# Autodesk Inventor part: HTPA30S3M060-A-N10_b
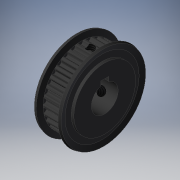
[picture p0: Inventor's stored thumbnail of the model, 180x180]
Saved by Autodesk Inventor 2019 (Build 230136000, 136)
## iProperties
Created: 2022-11
Part Number: HTPA30S3M060-A-N10_b
Material: Generic
Catalog Web Link: www.cadenas.de
Description: HTPA__S3M060, HTPA__S3M100, HTPA__S3M150, HTPB__S3M060, HTPB__S3M100, HTPB__S3M150, HTPK__S3M060, HTPK__S3M100, HTPK__S3M150, HTPN__S3M060, HTPN__S3M100, HTPN__
Vendor: MISUMI
Document SubType Name: Modeling
Designer: psAdmin
Manufacturer: MISUMI
Mass: 5.31734 g
Surface Area: 36.0109 cm^2
Volume: 5.31734 cm^3
Density: 1 g/cm^3
Appearance: PSOLRGB-175-175-175
Category: PARTsolutions
Company: MISUMI
Title: HTPA30S3M060-A-N10
Author: Cadenas PARTsolutions
Comments: High Torque Timing Pulleys S3M Type
PSOL_IDENT_0: {$CADENAS_DATA/23d-libs/misumi/metric/51_timing_pulleys/htpk_s3m/htpa_s3m.prj},837 {VTYP=3D},{NB=HTP
PSOL_IDENT_1: A30S3M060-A-N10_b},{LINA=HTPA30S3M060-A-N10},{NN=HTPA__S3M060, HTPA__S3M100, HTPA__S3M150, HTPB__S3M
PSOL_IDENT_2: 060, HTPB__S3M100, HTPB__S3M150, HTPK__S3M060, HTPK__S3M100, HTPK__S3M150, HTPN__S3M060, HTPN__S3M10
PSOL_IDENT_3: 0, HTPN__S3M150, HTPT__S3M060, HTPT__S3M100, HTPT__S3M150, HTPM__S3M060, HTPM__S3M100, HTPM__S3M150,
PSOL_IDENT_4: HTPP__S3M060, HTPP__S3M100, HTPP__S3M150, HTPS__S3M060, HTPS__S3M100, KHTPA__S3M060, KHTPA__S3M100,
PSOL_IDENT_5: KHTPA__S3M150, KHTPK__S3M060, KHTPK__S3M100, KHTPK__S3M150_body},{DATE=28.10.2022 00:10:57},{GEOMDA
PSOL_IDENT_6: TE=11.11.2021 09:52:43},{VERSION=},{LINEID=160},{WBVAR=MATP,ST,TNW,PS,SBS,DD,Z,J,Q,R,S,T,ALT1,ALT2,M
PSOL_IDENT_7: ,QSC,QFC,QTC,ALT3,K,KSC,KFC,KTC,ALT4,ZM,ZSC,ZFC,ZTC,ALT5,ALT6,ALT7,FC,ALT8,SRG,ALT9,BTC,TL,ALT10,TPC
PSOL_IDENT_8: ,ALT11,BC,ALT12,SLH,ALT13,BN},{WBNUMERIC=DD,Z,J,Q,R,S,T,QSC,QFC,QTC,K,KSC,KFC,KTC,ZSC,ZFC,ZTC,FC,SRG
PSOL_IDENT_9: ,BTC,TL,BC,SLH,BN}  {NB=HTPA30S3M060-A-N10_b},{LINA=HTPA30S3M060-A-N10},{KT=DUMMY},{PN=HTPA30S3M060-
PSOL_IDENT_10: A-N10},{TYPE=HTPA},{MATP=A2017},{MATPALG='A2017','Aluminum Alloy 2000 series','S45C','1045 Carbon St
PSOL_IDENT_11: eel Equivalent','SUS304','304 Stainless Steel','A6000','6000 Series Aluminum Alloy'},{ST=CA},{STALG=
PSOL_IDENT_12: 'CA','Clear Anodize','BA','Black Anodize','HAT','Hard Clear Anodize','ENP','Electroless Nickel Plat
PSOL_IDENT_13: ing' },{NT=30},{TNW=S3M060},{TNWALG= 'S3M060','S3M100','S3M150'    },{BW=6},{PS=A},{PSALG='A','B'},{
PSOL_IDENT_14: SBS=N},{SBSALG= 'H','Round Hole','P','Round Hole + Tap','N','New JIS Keywayed Bore + Tap (Standard)'
PSOL_IDENT_15: ,'NK','New JIS Keywayed Bore + Tap (width 4.0mm, height 1.8mm)','C','Old JIS Keywayed Bore + Tap','V'
PSOL_IDENT_16: ,'Stepped Hole', 'Y','Both Ends Stepped Hole','WB', 'Double Stepped Hole' },{SHSA= 'H','Round Hole','
PSOL_IDENT_17: P','Round Hole + Tap','N','New JIS Keywayed Bore + Tap (Standard)','NK','New JIS Keywayed Bore + Tap
PSOL_IDENT_18: (width 4.0mm, height 1.8mm)','C','Old JIS Keywayed Bore + Tap','V','Stepped Hole', 'Y','Both Ends S
PSOL_IDENT_19: tepped Hole','WB', 'Double Stepped Hole' },{SHSB= 'H','Round Hole','P','Round Hole + Tap','N','New J
PSOL_IDENT_20: IS Keywayed Bore + Tap (Standard)','NK','New JIS Keywayed Bore + Tap (width 4.0mm, height 1.8mm)','C'
PSOL_IDENT_21: ,'Old JIS Keywayed Bore + Tap','V','Stepped Hole', 'F','Stepped Hole (Counterbore holes on the boss
PSOL_IDENT_22: side)'},{SHSK= '','' },{SBSPN=-N10},{DD=10.00},{DDALG=[8:8/1],[10:14/1]},{DDHA=[6:6/1],6.35,[7:12/1]
PSOL_IDENT_23: ,12.7,[13:19/1]},{DDHBK=0},{DDPA=[6:6/1],6.35,[7:12/1],12.7,[13:19/1]},{DDPBK=0},{DDNA=[8:8/1],[10:1
PSOL_IDENT_24: 4/1]},{DDNBK=0},{DDNK=10},{DDCA=[10:10/1],[12:12/1]},{DDCBK=0},{DDVA=[6:6/1],6.35,[7:12/1],12.7,[13:
PSOL_IDENT_25: 17/1]},{DDVF=[6:6/1],6.35,[7:12/1],12.7,[13:14/1]},{DDY=[6:17/1]},{DDWB=[6:15/1]},{Z=0},{ZALG=[0]},{
PSOL_IDENT_26: ZQRMIN=12},{ZAMAX=19},{ZBMAX=16},{DDZ=10},{J=0.0},{JALG=[0]},{JMAX=9},{JMIN=2},{JPN=},{QRMAX=19},{QR
PSOL_IDENT_27: MIN=12},{WBRMAX=-2.00},{WBQMIN=14},{Q=0},{QALG=[0]},{QPN=},{R=0},{RALG=[0]},{S=0.0},{SALG=[0]},{SPN=
PSOL_IDENT_28: },{SMAX=5},{T=0.0},{TALG=[0]},{TPN=},{TMAX=8},{A=7},{W=11},{L=0},{PD=28.65},{OD=27.89},{D=0},{DALG=2
PSOL_IDENT_29: 0},{DE=23},{F=32},{E=23},{BBK=3.000},{TTK=1.4},{TT=1},{ANG=120},{WL=11},{ALT1=},{ALT1ALG= '','w/o KC
PSOL_IDENT_30: 90 (Set Screw Angle)','KC90','with KC90 (Set Screw Angle)' },{ALT1PN=},{ALT2=},{ALT2ALG= '','Not app
PSOL_IDENT_31: licable' },{M=N/A},{MALG= 'N/A' },{MFTALG= 'N/A' },{MSALG= 'N/A' },{M3D=0.000},{KDML=0},{ML=0},{MUL=
PSOL_IDENT_32: 0},{PITCH=0},{QSC=0.0},{QSCALG=0},{QFC=0.0},{QFCALG=0},{QTC=0.0},{QTCALG=0},{QPCDMIN=0},{QPCDMINALG=
PSOL_IDENT_33: 0},{QPCDMAX=19},{ALT2PN=},{ALT3=},{ALT3ALG= '','Not applicable' },{K=0.0},{KALG=0},{KMIN=4},{KFTMAX=
PSOL_IDENT_34: 0.0},{KSMAX=0.0},{KSC=0.0},{KSCALG=0},{KFC=0.0},{KFCALG=0},{KTC=0.0},{KTCALG=0},{KPCDMIN=14},{KPCDMI
PSOL_IDENT_35: NALG=14},{KPCDMAX=19},{KSCMIN=14.0},{KSCMINALG=14},{ALT3PN=},{ALT4=},{ALT4ALG= '','Not applicable' }
PSOL_IDENT_36: ,{ALT4MIN=20.5},{ALT4MAX=12.5},{ZM=N/A},{ZMALG= 'N/A' },{ZMSALG= 'N/A' },{ZMFTALG= 'N/A' },{ZMDD1=0.
PSOL_IDENT_37: 0},{ZMDD2=0.0},{ZMHH=0.0},{ZSC=0.0},{ZSCALG=[0]},{ZFC=0.0},{ZFCALG=[0]},{ZTC=0.0},{ZTCALG=[0]},{ZPCD
PSOL_IDENT_38: MIN=0},{ZPCDMINALG=0},{ZPCDMAX=19},{ALT4PN=},{ALT5=},{ALT5ALG= '','Flange Attached','NFC','with NFC
PSOL_IDENT_39: (Flange not Attached)' },{ALT5PN=},{ALT6=},{ALT6ALG= '','w/o Flange Attached on One Side Only','RFC'
PSOL_IDENT_40: ,'with RFC (Flange Attached on The Boss Side Only)','LFC','with LFC (Flange Attached on The Opposite
PSOL_IDENT_41: Side Only)' },{ALT6PN=},{ALT7=},{ALT7ALG= '','w/o FC (Flange Cut)','FC','with FC (Flange Cut)' },{F
PSOL_IDENT_42: C=0.0},{FCALG=0},{FCMIN=29.0},{FCMAX=30.0},{ALT7PN=},{ALT8=},{ALT8ALG= '','Not applicable' },{ALT8AL
PSOL_IDENT_43: GALG=19},{ALT8DD2=0},{ALT8MM=0},{ALT8NN=0},{QC=0},{KC=0},{ZC=0},{SRG=0.0},{SRGALG=[0]},{SRGMAX1=0},{
PSOL_IDENT_44: SRGMAX=0},{DD2=0.0},{MM=0.00},{NN=0.00},{ALT8PN=},{ALT9ALG= '','Not applicable' },{ALT9=},{BTC9=11},
PSOL_IDENT_45: {TL9=1},{BTC=0},{BTCALG=[0]},{TL=0.0},{TLALG=0},{TLMIN=1.0},{TLMAX=-11.5},{BTCL=0},{BTCD=0},{BTCDALG=
PSOL_IDENT_46: 20.000},{ALT9PN=},{WLBCTL=11},{ALT10=},{ALT10ALG= '','w/o TPC (Tapped Hole Dimension)','TPC','with T
PSOL_IDENT_47: PC (Tapped Hole Dimension)' },{TPC=N/A},{TPCALG= 'N/A' },{TPCM=4},{ALT10PN=},{ALT11=},{ALT11ALG= '','
PSOL_IDENT_48: Not applicable' },{BC=0.0},{BCALG=0},{BCMIN=7},{BCMAX=-11.5},{BCPLANE=5.5},{M1WBC=5.5},{ALT11PN=},{A
PSOL_IDENT_49: LT12=},{ALT12ALG= '','w/o SLH (Set Screw Length)','SLH','with SLH (Set Screw Length)' },{SLH=0},{SLH
PSOL_IDENT_50: ALG=[0]},{ALT12PN=},{AC=M4x3},{M1=4},{M1L=3},{TAP=0.000},{KYY=5},{KTT=8.945},{PLANE=11},{CD=0},{ALT1
PSOL_IDENT_51: 3=},{ALT13ALG= '', 'Not applicable' },{BN=0.0},{BNALG=0},{BNMIN=-10.5},{BNMAX=-1.0},{ALT13PN=}
NB: HTPA30S3M060-A-N10_b
NN: 0
NT: 30
NBSYN: $PN._b
LINA: HTPA30S3M060-A-N10
CATALOG: Misumi
PN: HTPA30S3M060-A-N10
MATP: Aluminum Alloy 2000 series
ST: Clear Anodize
TNW: S3M060
BW: 6
PS: A
SBS: New JIS Keywayed Bore + Tap (Standard)
DD: 10
Z: 0
J: 0
Q: 0
R: 0
S: 0
T: 0
A: 7
W: 11
L: 0
PD: 28.65
OD: 27.89
D: 0
F: 32
E: 23
TT: 1
ALT1: w/o KC90 (Set Screw Angle)
ALT2: Not applicable
M: N/A
QSC: 0
QFC: 0
QTC: 0
ALT3: Not applicable
K: 0
KSC: 0
KFC: 0
KTC: 0
ALT4: Not applicable
ZM: N/A
ZMDD1: 0
ZMDD2: 0
ZMHH: 0
ZSC: 0
ZFC: 0
ZTC: 0
ALT5: Flange Attached
ALT6: w/o Flange Attached on One Side Only
ALT7: w/o FC (Flange Cut)
FC: 0
ALT8: Not applicable
SRG: 0
DD2: 0
MM: 0
ALT9: Not applicable
BTC: 0
TL: 0
BTCL: 0
BTCD: 0
ALT10: w/o TPC (Tapped Hole Dimension)
TPC: N/A
ALT11: Not applicable
BC: 0
ALT12: w/o SLH (Set Screw Length)
SLH: 0
AC: M4x3
ALT13: Not applicable
BN: 0
SUPPLIER: MISUMI
ARTICLENO: HTPA30S3M060-A-N10_b
BOMINFO: HTPA30S3M060-A-N10
CREATOR: CADENAS GmbH
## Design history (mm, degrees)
sketch "_____1"
  geometry: L1 (11, 0)-(0, 0); L2 (0, 0)-(0, 11.5); L3 (0, 11.5)-(1, 11.5); L4 (1, 11.5)-(1, 13.813); L5 (1, 13.813)-(0.483, 15.741); L6 (0.483, 15.741)-(1.449, 16); L7 (1.449, 16)-(2, 13.945); L8 (2, 13.945)-(9, 13.945); L9 (9, 13.945)-(9.551, 16); L10 (9.551, 16)-(10.517, 15.741); L11 (10.517, 15.741)-(10, 13.813); L12 (10, 13.813)-(10, 11.5); L13 (10, 11.5)-(11, 11.5); L14 (11, 11.5)-(11, 0); L15 (11, 0)-(0, 0)
  constraints: 30 end point
revolve "Revolution1" sketch "_____1" stored, may be unused: angle "d0" = 360 deg
sketch "Sketch2"
  geometry: 1 further point
hole "Hole1" sketch "Sketch2" at (0, 0) diameter "d1" = 10; stored, may be unused: countersink angle "d5" = 90 deg, drill point angle "d7" = 0 deg; dims "d2" = 6, "d3" = 4, "d4" = 2, "d6" = 11
sketch "_____6"
  geometry: C1 r 18.945 at (0, 0); A1 r 13.945 centre (0, 0) between (-13.943, 0.259) and (-13.943, -0.259); A2 r 0.28 centre (-13.663, -0.254) between (-13.943, -0.259) and (-13.718, -0.528); A3 r 1.975 centre (-14.112, -2.464) between (-12.845, -0.948) and (-13.718, -0.528); A4 r 0.15 centre (-12.941, -1.063) between (-12.792, -1.051) and (-12.845, -0.948); A5 r 12.835 centre (0, 0) between (-12.792, -1.051) and (-12.731, -1.632); A6 r 0.15 centre (-12.88, -1.651) between (-12.762, -1.743) and (-12.731, -1.632); A7 r 1.975 centre (-14.315, -0.524) between (-13.528, -2.336) and (-12.762, -1.743); A8 r 0.28 centre (-13.417, -2.592) between (-13.528, -2.336) and (-13.692, -2.646); A9 r 13.945 centre (0, 0) between (-13.692, -2.646) and (-13.584, -3.152); A10 r 0.28 centre (-13.311, -3.089) between (-13.584, -3.152) and (-13.309, -3.369); A11 r 1.975 centre (-13.291, -5.344) between (-12.367, -3.598) and (-13.309, -3.369); A12 r 0.15 centre (-12.438, -3.731) between (-12.294, -3.687) and (-12.367, -3.598); A13 r 12.835 centre (0, 0) between (-12.294, -3.687) and (-12.113, -4.243); A14 r 0.15 centre (-12.255, -4.293) between (-12.12, -4.359) and (-12.113, -4.243); A15 r 1.975 centre (-13.894, -3.489) between (-12.747, -5.097) and (-12.12, -4.359); A16 r 0.28 centre (-12.585, -5.325) between (-12.747, -5.097) and (-12.842, -5.434); A17 r 13.945 centre (0, 0) between (-12.842, -5.434) and (-12.632, -5.907); A18 r 0.28 centre (-12.378, -5.789) between (-12.632, -5.907) and (-12.318, -6.062); A19 r 1.975 centre (-11.89, -7.99) between (-11.349, -6.091) and (-12.318, -6.062); A20 r 0.15 centre (-11.39, -6.235) between (-11.259, -6.163) and (-11.349, -6.091); A21 r 12.835 centre (0, 0) between (-11.259, -6.163) and (-10.967, -6.669); A22 r 0.15 centre (-11.095, -6.747) between (-10.949, -6.783) and (-10.967, -6.669); A23 r 1.975 centre (-12.865, -6.302) between (-11.409, -7.636) and (-10.949, -6.783); A24 r 0.28 centre (-11.202, -7.825) between (-11.409, -7.636) and (-11.432, -7.986); A25 r 13.945 centre (0, 0) between (-11.432, -7.986) and (-11.128, -8.405); A26 r 0.28 centre (-10.904, -8.236) between (-11.128, -8.405) and (-10.788, -8.491); A27 r 1.975 centre (-9.968, -10.288) between (-9.835, -8.317) and (-10.788, -8.491); A28 r 0.15 centre (-9.845, -8.467) between (-9.731, -8.369) and (-9.835, -8.317); A29 r 12.835 centre (0, 0) between (-9.731, -8.369) and (-9.34, -8.803); A30 r 0.15 centre (-9.45, -8.906) between (-9.3, -8.912) and (-9.34, -8.803); A31 r 1.975 centre (-11.273, -8.839) between (-9.572, -9.841) and (-9.3, -8.912); A32 r 0.28 centre (-9.331, -9.984) between (-9.572, -9.841) and (-9.522, -10.188); A33 r 13.945 centre (0, 0) between (-9.522, -10.188) and (-9.137, -10.535); A34 r 0.28 centre (-8.954, -10.323) between (-9.137, -10.535) and (-8.787, -10.548); A35 r 1.975 centre (-7.612, -12.135) between (-7.891, -10.18) and (-8.787, -10.548); A36 r 0.15 centre (-7.869, -10.329) between (-7.779, -10.209) and (-7.891, -10.18); A37 r 12.835 centre (0, 0) between (-7.779, -10.209) and (-7.306, -10.553); A38 r 0.15 centre (-7.391, -10.676) between (-7.244, -10.65) and (-7.306, -10.553); A39 r 1.975 centre (-9.189, -10.989) between (-7.317, -11.616) and (-7.244, -10.65); A40 r 0.28 centre (-7.051, -11.705) between (-7.317, -11.616) and (-7.196, -11.945); A41 r 13.945 centre (0, 0) between (-7.196, -11.945) and (-6.747, -12.204); A42 r 0.28 centre (-6.612, -11.959) between (-6.747, -12.204) and (-6.402, -12.145); A43 r 1.975 centre (-4.922, -13.453) between (-5.602, -11.598) and (-6.402, -12.145); A44 r 0.15 centre (-5.55, -11.739) between (-5.486, -11.604) and (-5.602, -11.598); A45 r 12.835 centre (0, 0) between (-5.486, -11.604) and (-4.952, -11.841); A46 r 0.15 centre (-5.01, -11.98) between (-4.871, -11.924) and (-4.952, -11.841); A47 r 1.975 centre (-6.704, -12.66) between (-4.741, -12.884) and (-4.871, -11.924); A48 r 0.28 centre (-4.463, -12.916) between (-4.741, -12.884) and (-4.555, -13.18); A49 r 13.945 centre (0, 0) between (-4.555, -13.18) and (-4.062, -13.34); A50 r 0.28 centre (-3.981, -13.072) between (-4.062, -13.34) and (-3.737, -13.21); A51 r 1.975 centre (-2.018, -14.182) between (-3.068, -12.509) and (-3.737, -13.21); A52 r 0.15 centre (-2.988, -12.637) between (-2.954, -12.491) and (-3.068, -12.509); A53 r 12.835 centre (0, 0) between (-2.954, -12.491) and (-2.382, -12.612); A54 r 0.15 centre (-2.41, -12.759) between (-2.285, -12.676) and (-2.382, -12.612); A55 r 1.975 centre (-3.925, -13.777) between (-1.959, -13.588) and (-2.285, -12.676); A56 r 0.28 centre (-1.68, -13.561) between (-1.959, -13.588) and (-1.715, -13.839); A57 r 13.945 centre (0, 0) between (-1.715, -13.839) and (-1.2, -13.893); A58 r 0.28 centre (-1.176, -13.614) between (-1.2, -13.893) and (-0.909, -13.698); A59 r 1.975 centre (0.975, -14.292) between (-0.4, -12.874) and (-0.909, -13.698); A60 r 0.15 centre (-0.295, -12.982) between (-0.292, -12.832) and (-0.4, -12.874); A61 r 12.835 centre (0, 0) between (-0.292, -12.832) and (0.292, -12.832); A62 r 0.15 centre (0.295, -12.982) between (0.4, -12.874) and (0.292, -12.832); A63 r 1.975 centre (-0.975, -14.292) between (0.909, -13.698) and (0.4, -12.874); A64 r 0.28 centre (1.176, -13.614) between (0.909, -13.698) and (1.2, -13.893)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; 1 further point
  constraints: 480 point on circle, 241 centre point
extrude "Extrusion1" cut sketch "_____6" distance "d8" = 7; taper "d9" = 0 deg
sketch "_____10"
  geometry: L1 (-1.5, 6.4)-(-1.5, 0); L2 (-1.5, 0)-(1.5, 0); L3 (1.5, 0)-(1.5, 6.4); L4 (1.5, 6.4)-(-1.5, 6.4)
  constraints: 8 end point
extrude "Extrusion2" cut sketch "_____10" distance "d10" = 11; taper "d11" = 0 deg
sketch "_____18"
  geometry: L1 (0, 0)-(0, 13.945); L2 (0, 13.945)-(1.621, 13.945); L3 (1.621, 13.945)-(1.621, 0); L4 (1.621, 0)-(0, 0); L5 (0, 0)-(0, 13.945)
  constraints: 10 end point
revolve "Revolution2" sketch "_____18" stored, may be unused: angle "d12" = 360 deg
thread "Thread1" dims "d13" = 8.945, "d14" = 0
sketch "_____19"
  geometry: L1 (0, 0)-(12.077, -6.973); L2 (12.077, -6.973)-(11.266, -8.376); L3 (11.266, -8.376)-(-0.811, -1.404); L4 (-0.811, -1.404)-(0, 0); L5 (0, 0)-(12.077, -6.973)
  constraints: 10 end point
revolve "Revolution3" sketch "_____19" stored, may be unused: angle "d15" = 360 deg
thread "Thread2" dims "d16" = 8.945, "d17" = 0.17552
node "to_belt_XY"
node "to_belt_YZ"
node "to_belt_ZX"
node "to_belt_X"
node "to_belt_Y"
node "to_belt_Z"
node "to_belt_Center"
node "to_screw1_XY"
node "to_screw1_YZ"
node "to_screw1_ZX"
node "to_screw1_X"
node "to_screw1_Y"
node "to_screw1_Z"
node "to_screw1_Center"
node "to_screw2_XY"
node "to_screw2_YZ"
node "to_screw2_ZX"
node "to_screw2_X"
node "to_screw2_Y"
node "to_screw2_Z"
node "to_screw2_Center"
body "Solid1"
other parameters: "d18" = 0
